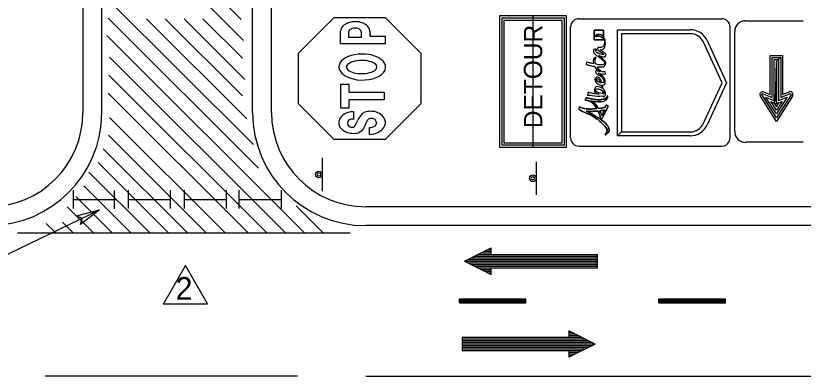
# Model space of a CAD drawing. Extents: x 1482 to 1692, y 225 to 494.
# Drawn here: x 1536.8 to 1587.3, y 314.2 to 337.4 of the extents above; entities that cross this region are included whole.
import ezdxf

# ---------------------------------------------------------------- set-up
doc = ezdxf.new("R2010")
doc.units = 0
for name, color, linetype in [('Level 10', 7, 'Continuous'), ('Level 17', 7, 'Continuous'), ('Level 2', 7, 'Continuous'), ('Level 53', 7, 'Continuous'), ('Level 60', 7, 'Continuous')]:
    doc.layers.add(name, color=color, linetype=linetype)

msp = doc.modelspace()

# ---------------------------------------------------------------- linework, layer by layer
at = {"layer": 'Level 10'}
for p, q in [((1540.474, 324.994), (1540.474, 326.173)), ((1543.997, 324.994), (1543.997, 326.173)), ((1546.697, 324.994), (1546.697, 326.173)), ((1547.586, 324.994), (1547.586, 326.173)), ((1550.286, 324.994), (1550.286, 326.173)), ((1551.109, 324.994), (1551.109, 326.173)), ((1553.809, 324.994), (1553.809, 326.173)), ((1540.474, 325.58), (1543.174, 325.58)), ((1543.997, 325.58), (1546.697, 325.58)), ((1547.586, 325.58), (1550.286, 325.58)), ((1551.109, 325.58), (1553.809, 325.58))]:
    msp.add_line(p, q, dxfattribs=at)
at = {"layer": 'Level 17'}
for p, q in [((1569.955, 328.928), (1569.955, 337.365)), ((1583.587, 337.047), (1587.284, 337.047)), ((1557.604, 335.58), (1557.604, 336.384)), ((1558.12, 336.312), (1558.12, 336)), ((1558.12, 336.312), (1558.12, 336)), ((1558.12, 336), (1558.956, 336)), ((1558.12, 336), (1558.956, 336)), ((1558.956, 336), (1558.956, 336.306)), ((1558.956, 336), (1558.956, 336.306)), ((1559.491, 336.343), (1559.498, 336.057)), ((1559.498, 336.057), (1559.498, 336.357)), ((1559.498, 336.057), (1560.478, 336.057)), ((1560.478, 336.057), (1560.478, 335.58)), ((1582.901, 329.932), (1582.901, 336.369)), ((1560.478, 335.58), (1557.604, 335.58)), ((1585.163, 332.308), (1585.163, 334.824)), ((1585.163, 334.824), (1585.963, 334.824)), ((1585.963, 334.824), (1585.963, 332.314)), ((1557.504, 334.053), (1557.502, 334.068)), ((1557.992, 334.033), (1557.988, 334.053)), ((1557.631, 331.446), (1557.631, 332.976)), ((1557.631, 332.976), (1558.146, 332.976)), ((1558.146, 332.976), (1558.146, 332.472)), ((1558.146, 332.472), (1560.394, 332.472)), ((1560.394, 332.472), (1560.394, 331.974)), ((1584.703, 332.5), (1585.163, 332.308)), ((1585.963, 332.308), (1586.425, 332.506)), ((1560.394, 331.974), (1558.134, 331.974)), ((1558.134, 331.974), (1558.134, 331.446)), ((1585.567, 330.586), (1584.536, 332.199)), ((1586.591, 332.199), (1585.567, 330.586)), ((1558.134, 331.446), (1557.631, 331.446)), ((1558.434, 331.212), (1558.434, 330.72)), ((1559.466, 329.755), (1559.466, 330.205)), ((1560.034, 329.898), (1560.032, 329.895)), ((1587.284, 329.248), (1583.587, 329.248)), ((1556.457, 326.107), (1556.457, 328.24)), ((1570.177, 325.863), (1570.177, 327.996)), ((1543.112, 324.972), (1543.112, 326.151)), ((1535.698, 321.794), (1542.151, 324.898))]:
    msp.add_line(p, q, dxfattribs=at)
for points in [[(1560.458, 337.269), (1562.752, 334.975), (1562.752, 331.709), (1560.458, 329.415), (1557.192, 329.415), (1554.9, 331.709), (1554.9, 334.975), (1557.192, 337.269)], [(1567.801, 337.359), (1567.801, 328.934), (1572.109, 328.934), (1572.109, 337.359)], [(1567.942, 337.22), (1567.942, 329.074), (1571.968, 329.074), (1571.968, 337.22)], [(1568.083, 337.078), (1568.083, 329.214), (1571.828, 329.214), (1571.828, 337.078)], [(1542.151, 324.898), (1540.934, 323.968), (1541.023, 324.355), (1540.665, 324.527)]]:
    msp.add_lwpolyline(points, close=True, dxfattribs=at)
for points in [[(1585.841, 334.689), (1585.841, 332.116), (1586.437, 332.372), (1586.501, 332.302), (1585.567, 330.824), (1584.619, 332.308), (1584.657, 332.379), (1585.291, 332.116), (1585.291, 334.695), (1585.841, 334.689), (1585.707, 334.568), (1585.707, 331.924), (1586.258, 332.148), (1585.567, 331.066), (1584.875, 332.148), (1585.425, 331.924), (1585.425, 334.568), (1585.707, 334.568), (1585.579, 334.432), (1585.579, 331.713), (1585.925, 331.86), (1585.567, 331.304), (1585.202, 331.874), (1585.406, 331.79), (1585.567, 331.534), (1585.727, 331.778), (1585.561, 331.726), (1585.406, 331.79), (1585.496, 331.918), (1585.561, 334.426), (1585.579, 334.432)], [(1585.841, 334.689), (1585.841, 332.116)]]:
    msp.add_lwpolyline(points, dxfattribs=at)
for centre, radius in [((1556.218, 327.178), 0.213), ((1556.218, 327.178), 0.107), ((1569.938, 326.934), 0.213), ((1569.938, 326.934), 0.107)]:
    msp.add_circle(centre, radius, dxfattribs=at)
for centre, radius, start, end in [((1558.358, 336.182), 0.778, 103.0674, 123.762), ((1558.587, 335.484), 1.512, 93.3903, 105.6597), ((1558.558, 335.78), 1.215, 79.7521, 92.7916), ((1558.558, 335.78), 1.215, 79.7521, 92.7916), ((1558.463, 335.418), 1.588, 68.3153, 78.6699), ((1583.585, 336.363), 0.692, 90, 180), ((1558.077, 336.342), 0.477, 134.8528, 175.0441), ((1558.286, 336.192), 0.732, 119.2241, 138.5308), ((1558.286, 336.192), 0.732, 119.2241, 138.5308), ((1558.392, 336.264), 0.283, 125.1198, 169.3117), ((1558.392, 336.264), 0.283, 125.1198, 169.3117), ((1558.476, 336.132), 0.44, 98.6031, 124.217), ((1558.476, 336.132), 0.44, 98.6031, 124.217), ((1558.533, 336.116), 0.468, 80.3417, 105.2342), ((1558.533, 336.116), 0.468, 80.3417, 105.2342), ((1558.59, 336.16), 0.418, 56.5086, 87.0313), ((1558.59, 336.16), 0.418, 56.5086, 87.0313), ((1558.638, 336.24), 0.325, 11.9191, 55.7868), ((1558.638, 336.24), 0.325, 11.9191, 55.7868), ((1558.767, 336.173), 0.774, 48.2922, 68.6031), ((1558.767, 336.173), 0.774, 48.2922, 68.6031), ((1558.989, 336.374), 0.478, 25.3838, 52.6188), ((1558.806, 336.231), 0.706, 16.602, 29.8091), ((1559.328, 336.373), 0.166, 349.7909, 23.5419), ((1584.703, 332.303), 0.199, 90.1051, 212.4986), ((1586.425, 332.306), 0.199, 327.5038, 90.1058), ((1558.022, 330.506), 0.532, 136.1369, 211.3987), ((1558.314, 330.284), 0.898, 104.564, 139.0063), ((1558.455, 329.966), 1.243, 90.6952, 107.1452), ((1559.8, 330.227), 1.175, 136.2465, 157.9263), ((1557.651, 332.628), 2.053, 309.479, 313.4261), ((1559.537, 330.014), 1.223, 95.9097, 111.9865), ((1559.534, 329.504), 1.731, 81.247, 93.9864), ((1559.413, 329.91), 1.361, 55.5092, 73.2894), ((1559.736, 330.391), 0.782, 23.1413, 54.9906), ((1558.325, 330.46), 0.277, 137.3017, 199.0119), ((1558.303, 330.481), 0.264, 203.8064, 262.2407), ((1558.373, 330.331), 0.405, 80.4412, 129.3244), ((1557.123, 331.213), 1.68, 327.9816, 340.979), ((1554.114, 332.527), 5.521, 334.4624, 338.8312), ((1559.599, 330.443), 0.348, 124.2083, 164.1552), ((1559.562, 330.453), 0.319, 82.5761, 120.4776), ((1559.6, 330.357), 0.413, 56.253, 88.7323), ((1559.597, 330.492), 0.31, 5.4374, 44.0625), ((1559.571, 330.517), 0.335, 320.6966, 1.4573), ((1560.001, 330.506), 0.489, 322.0536, 22.7397), ((1558.295, 330.706), 0.87, 213.3662, 245.6734), ((1558.401, 331.04), 1.219, 247.7332, 267.1392), ((1558.341, 330.45), 0.242, 254.131, 328.1476), ((1558.434, 330.889), 1.071, 264.8171, 285.9183), ((1558.466, 330.575), 0.762, 290.4481, 325.1107), ((1559.473, 330.885), 0.685, 269.0172, 283.5172), ((1559.399, 331.257), 1.502, 272.3841, 294.9519), ((1559.602, 330.563), 0.344, 276.8728, 312.7449), ((1559.525, 330.839), 1.07, 298.4154, 323.6553), ((1583.585, 329.933), 0.692, 180, 270)]:
    msp.add_arc(centre, radius, start, end, dxfattribs=at)
for centre, major_axis, ratio, start_param, end_param in [((1558.999, 334.08), (1.497, -0.01), 0.558644, 0.656861, 3.168126), ((1558.965, 334.08), (0.977, 0.005), 0.432619, 0.881967, 3.190734), ((1558.999, 334.08), (1.497, -0.01), 0.558644, 4.129576, 6.939747), ((1558.965, 334.08), (0.977, 0.005), 0.432619, 3.890436, 7.165085), ((1558.999, 334.08), (1.497, -0.01), 0.558644, 3.185857, 4.129398), ((1558.965, 334.08), (0.977, 0.005), 0.432619, 3.239639, 3.888884)]:
    msp.add_ellipse(centre, major_axis=major_axis, ratio=ratio, start_param=start_param, end_param=end_param, dxfattribs=at)
at = {"layer": 'Level 2'}
for p, q in [((1541.08, 370.179), (1541.08, 331.153)), ((1542.29, 331.153), (1542.29, 370.179)), ((1551.968, 331.153), (1551.968, 370.179)), ((1553.177, 331.153), (1553.177, 370.179)), ((1549.117, 339.254), (1551.241, 337.13)), ((1542.708, 338.422), (1552.014, 329.114)), ((1549.117, 338.047), (1551.39, 335.774)), ((1542.708, 337.215), (1552.347, 327.575)), ((1545.156, 337.181), (1551.589, 330.747)), ((1546.362, 337.181), (1551.323, 332.221)), ((1547.569, 337.181), (1551.474, 333.275)), ((1548.775, 337.181), (1551.308, 334.647)), ((1572.884, 337.18), (1582.071, 337.18)), ((1572.366, 329.52), (1572.366, 336.662)), ((1572.366, 329.52), (1572.366, 336.662)), ((1575.37, 329.662), (1575.37, 336.478)), ((1575.37, 336.478), (1580.038, 336.478)), ((1582.589, 329.52), (1582.589, 336.662)), ((1542.62, 336.095), (1555.293, 323.424)), ((1580.038, 336.222), (1575.625, 336.222)), ((1575.625, 336.222), (1575.625, 329.918)), ((1582.075, 333.07), (1580.891, 335.673)), ((1581.123, 335.779), (1582.355, 333.07)), ((1542.791, 334.718), (1554.083, 323.424)), ((1542.745, 333.557), (1552.876, 323.424)), ((1580.891, 330.467), (1582.075, 333.07)), ((1582.355, 333.07), (1581.123, 330.361)), ((1542.703, 332.393), (1551.671, 323.424)), ((1542.778, 330.842), (1550.196, 323.424)), ((1575.37, 329.662), (1575.625, 329.918)), ((1575.625, 329.918), (1575.37, 329.662)), ((1575.625, 329.918), (1580.038, 329.918)), ((1542.715, 329.697), (1548.988, 323.424)), ((1580.038, 329.662), (1575.37, 329.662)), ((1572.884, 329.002), (1582.071, 329.002)), ((1542.384, 328.821), (1547.782, 323.424)), ((1542.062, 327.938), (1546.576, 323.424)), ((1541.46, 327.335), (1545.37, 323.424)), ((1541.136, 326.451), (1544.164, 323.424)), ((1540.618, 325.764), (1542.958, 323.424)), ((1540.071, 325.105), (1541.752, 323.424)), ((1554.757, 325.165), (1556.498, 323.424)), ((1620.696, 325.105), (1559.225, 325.105)), ((1538.726, 324.038), (1539.34, 323.424)), ((1539.769, 324.107), (1540.452, 323.424)), ((1620.696, 323.894), (1559.225, 323.894)), ((1536.893, 323.424), (1558.225, 323.424)), ((1565.561, 321.612), (1567.267, 322.465)), ((1567.054, 322.359), (1567.267, 322.359)), ((1567.267, 322.039), (1567.267, 322.465)), ((1565.988, 321.825), (1574.094, 321.825)), ((1566.201, 321.932), (1574.094, 321.932)), ((1566.414, 322.039), (1574.094, 322.039)), ((1566.628, 322.145), (1567.267, 322.145)), ((1566.841, 322.252), (1567.267, 322.252)), ((1567.267, 322.039), (1574.094, 322.039)), ((1574.094, 321.185), (1574.094, 322.039)), ((1565.561, 321.612), (1574.094, 321.612)), ((1565.561, 321.612), (1567.267, 320.759)), ((1565.774, 321.719), (1574.094, 321.719)), ((1565.774, 321.505), (1574.094, 321.505)), ((1565.988, 321.399), (1574.094, 321.399)), ((1566.201, 321.292), (1574.094, 321.292)), ((1566.414, 321.185), (1574.094, 321.185)), ((1566.628, 321.079), (1567.267, 321.079)), ((1566.841, 320.972), (1567.267, 320.972)), ((1567.054, 320.865), (1567.267, 320.865)), ((1567.267, 321.185), (1574.094, 321.185)), ((1567.267, 320.759), (1567.267, 321.185)), ((1565.231, 319.189), (1569.498, 319.189)), ((1565.231, 318.933), (1565.231, 319.189)), ((1565.231, 319.125), (1569.498, 319.125)), ((1565.231, 319.061), (1569.498, 319.061)), ((1565.231, 318.997), (1569.498, 318.997)), ((1565.231, 318.933), (1569.498, 318.933)), ((1569.498, 318.933), (1569.498, 319.189)), ((1578.031, 319.189), (1582.297, 319.189)), ((1578.031, 318.933), (1578.031, 319.189)), ((1578.031, 319.125), (1582.297, 319.125)), ((1578.031, 319.061), (1582.297, 319.061)), ((1578.031, 318.997), (1582.297, 318.997)), ((1578.031, 318.933), (1582.297, 318.933)), ((1582.297, 318.933), (1582.297, 319.189)), ((1573.948, 316.288), (1572.241, 317.141)), ((1572.241, 317.141), (1572.241, 316.715)), ((1572.454, 317.035), (1572.241, 317.035)), ((1572.668, 316.928), (1572.241, 316.928)), ((1572.881, 316.821), (1572.241, 316.821)), ((1572.241, 316.715), (1565.415, 316.715)), ((1565.415, 316.715), (1565.415, 315.861)), ((1573.094, 316.715), (1565.415, 316.715)), ((1573.308, 316.608), (1565.415, 316.608)), ((1573.521, 316.501), (1565.415, 316.501)), ((1573.734, 316.395), (1565.415, 316.395)), ((1573.948, 316.288), (1565.415, 316.288)), ((1573.948, 316.288), (1572.241, 315.435)), ((1573.734, 316.181), (1565.415, 316.181)), ((1573.521, 316.075), (1565.415, 316.075)), ((1573.308, 315.968), (1565.415, 315.968)), ((1572.241, 315.861), (1565.415, 315.861)), ((1573.094, 315.861), (1565.415, 315.861)), ((1572.241, 315.861), (1572.241, 315.435)), ((1572.881, 315.755), (1572.241, 315.755)), ((1572.668, 315.648), (1572.241, 315.648)), ((1572.454, 315.541), (1572.241, 315.541)), ((1554.854, 314.218), (1538.653, 314.218)), ((1559.225, 314.218), (1620.696, 314.218))]:
    msp.add_line(p, q, dxfattribs=at)
for centre, radius, start, end in [((1572.884, 336.662), 0.518, 90, 180), ((1582.071, 336.662), 0.518, 360, 90), ((1580.038, 335.285), 1.193, 24.4568, 90), ((1580.038, 335.285), 0.937, 24.4568, 90), ((1535.032, 331.153), 6.048, 270, 360), ((1535.032, 331.153), 7.258, 270, 360), ((1559.225, 331.153), 7.258, 180, 270), ((1559.225, 331.153), 6.048, 180, 270), ((1580.038, 330.855), 0.937, 270, 335.5432), ((1580.038, 330.855), 1.193, 270, 335.5432), ((1572.884, 329.52), 0.518, 180, 270), ((1582.071, 329.52), 0.518, 270, 360)]:
    msp.add_arc(centre, radius, start, end, dxfattribs=at)
at = {"layer": 'Level 53'}
msp.add_line((1574.481, 336), (1574.481, 335.85), dxfattribs=at)
msp.add_lwpolyline([(1574.481, 336), (1574.481, 336.44), (1573.873, 336.44), (1573.873, 335.832), (1574.481, 335.832), (1574.481, 335.85)], dxfattribs=at)
for points, degree in [([(1573.873, 335.832), (1573.873, 335.832), (1574.481, 335.832), (1574.481, 335.832), (1574.481, 335.832), (1574.481, 335.85), (1574.481, 335.85), (1574.402, 335.982), (1574.251, 336.071), (1574.126, 336.07), (1574.019, 336.07), (1574.025, 336.013), (1574.01, 336.02), (1573.966, 336.038), (1573.991, 336.173), (1574.143, 336.18), (1574.271, 336.187), (1574.396, 336.12), (1574.481, 336), (1574.481, 336), (1574.481, 336.44), (1574.481, 336.44), (1574.481, 336.44), (1573.873, 336.44), (1573.873, 336.44), (1573.873, 336.44), (1573.873, 335.832), (1573.873, 335.832)], 3), ([(1574.481, 335.85), (1574.402, 335.982), (1574.251, 336.071), (1574.126, 336.07), (1574.019, 336.07), (1574.025, 336.013), (1574.01, 336.02), (1573.966, 336.038), (1573.991, 336.173), (1574.143, 336.18), (1574.271, 336.187), (1574.396, 336.12), (1574.481, 336)], 3), ([(1574.25, 335.189), (1574.375, 335.203), (1574.591, 335.287), (1574.591, 335.624), (1574.591, 335.776), (1574.549, 335.904), (1574.481, 336)], 3), ([(1574.535, 335.662), (1574.535, 335.412), (1574.341, 335.348), (1574.245, 335.336), (1574.181, 335.328), (1574.089, 335.342), (1574.101, 335.231), (1574.11, 335.154), (1574.26, 335.084), (1574.386, 334.987), (1574.495, 334.903), (1574.485, 334.865), (1574.391, 334.885), (1574.275, 334.909), (1574.001, 335.006), (1573.981, 335.118), (1573.971, 335.17), (1574.062, 335.188), (1574.005, 335.212), (1573.949, 335.236), (1573.826, 335.214), (1573.826, 335.098), (1573.826, 335.017), (1573.912, 334.92), (1574.009, 334.841), (1574.094, 334.772), (1574.61, 334.421), (1574.499, 334.274), (1574.447, 334.206), (1574.235, 334.211), (1573.985, 334.254)], 3), ([(1574.481, 335.85), (1574.514, 335.794), (1574.535, 335.73), (1574.535, 335.662)], 2), ([(1574.177, 334.821), (1574.353, 334.743), (1574.578, 334.698), (1574.613, 334.816), (1574.653, 334.953), (1574.425, 335.062), (1574.25, 335.189)], 3), ([(1573.834, 334.284), (1573.753, 334.302), (1573.67, 334.322), (1573.59, 334.345), (1573.517, 334.365), (1573.39, 334.425), (1573.366, 334.268), (1573.358, 334.218), (1573.382, 334.239), (1573.45, 334.223), (1573.574, 334.192), (1573.736, 334.154), (1573.898, 334.126)], 3), ([(1573.985, 334.254), (1573.918, 334.429), (1573.94, 334.574), (1573.979, 334.656), (1573.998, 334.696), (1573.996, 334.702), (1573.951, 334.685), (1573.886, 334.659), (1573.783, 334.519), (1573.83, 334.3), (1573.831, 334.294), (1573.833, 334.289), (1573.834, 334.284)], 3), ([(1574.062, 334.103), (1574.298, 334.075), (1574.509, 334.085), (1574.576, 334.192), (1574.699, 334.388), (1574.375, 334.667), (1574.177, 334.821)], 3), ([(1573.898, 334.126), (1573.973, 333.997), (1574.097, 333.877), (1574.261, 333.789)], 2), ([(1574.14, 333.677), (1574.287, 333.663), (1574.606, 333.567), (1574.59, 333.73), (1574.583, 333.793), (1574.573, 333.766), (1574.518, 333.77), (1574.326, 333.784), (1574.162, 333.944), (1574.062, 334.103)], 3), ([(1574.373, 333.06), (1574.366, 333.086), (1574.357, 333.11), (1574.348, 333.129), (1574.242, 333.37), (1574.081, 333.453), (1573.983, 333.392), (1573.89, 333.334), (1573.918, 333.168), (1574.056, 333.037), (1574.124, 332.972), (1574.241, 332.922), (1574.348, 332.916)], 3), ([(1574.261, 333.789), (1574.185, 333.804), (1574.102, 333.828), (1574.045, 333.83), (1573.986, 333.831), (1573.973, 333.791), (1573.969, 333.775), (1573.959, 333.74), (1573.976, 333.699), (1574.034, 333.658), (1574.169, 333.561), (1574.384, 333.439), (1574.474, 333.254), (1574.539, 333.121), (1574.474, 333.063), (1574.373, 333.06)], 3), ([(1574.408, 332.918), (1574.515, 332.931), (1574.597, 333.001), (1574.582, 333.164), (1574.56, 333.394), (1574.277, 333.599), (1574.14, 333.677)], 3), ([(1574.068, 333.189), (1573.994, 333.269), (1573.999, 333.309), (1574.019, 333.32), (1574.063, 333.343), (1574.216, 333.248), (1574.3, 333.066)], 3), ([(1574.3, 333.066), (1574.217, 333.082), (1574.127, 333.125), (1574.068, 333.189)], 2), ([(1574.348, 332.916), (1574.36, 332.861), (1574.37, 332.797), (1574.38, 332.726)], 2), ([(1574.446, 332.676), (1574.436, 332.757), (1574.423, 332.841), (1574.408, 332.918)], 2), ([(1574.199, 332.334), (1574.044, 332.346), (1573.856, 332.371), (1573.68, 332.406), (1573.607, 332.421), (1573.48, 332.471), (1573.456, 332.312), (1573.448, 332.261), (1573.471, 332.269), (1573.54, 332.273), (1573.632, 332.279), (1574.188, 332.177), (1574.432, 332.23)], 3), ([(1574.38, 332.726), (1574.196, 332.839), (1573.948, 332.829), (1573.907, 332.664), (1573.858, 332.472), (1574.044, 332.375), (1574.199, 332.334)], 3), ([(1574.415, 332.375), (1574.22, 332.4), (1573.949, 332.502), (1573.992, 332.628), (1574.017, 332.701), (1574.246, 332.663), (1574.398, 332.569)], 3), ([(1574.398, 332.569), (1574.404, 332.508), (1574.41, 332.443), (1574.415, 332.375)], 2), ([(1574.432, 332.23), (1574.454, 332.162), (1574.506, 332.134), (1574.56, 332.222), (1574.597, 332.283), (1574.61, 332.416), (1574.543, 332.551), (1574.519, 332.6), (1574.486, 332.641), (1574.446, 332.676)], 3), ([(1574.475, 332.369), (1574.474, 332.403), (1574.47, 332.457), (1574.464, 332.521)], 2), ([(1574.464, 332.521), (1574.501, 332.487), (1574.526, 332.45), (1574.532, 332.409)], 2), ([(1574.532, 332.409), (1574.536, 332.387), (1574.535, 332.369), (1574.533, 332.354)], 2), ([(1574.702, 332.187), (1574.692, 332.122), (1574.603, 332.036), (1574.456, 332.01), (1574.193, 331.964), (1573.933, 331.991), (1573.546, 332.069), (1573.472, 332.083), (1573.345, 332.133), (1573.321, 331.974), (1573.313, 331.924), (1573.338, 331.95), (1573.405, 331.936), (1573.694, 331.875), (1573.901, 331.639), (1574.041, 331.402), (1573.711, 331.377), (1573.344, 331.387), (1573.119, 331.449), (1572.929, 331.502), (1572.964, 331.564), (1572.924, 331.487), (1572.882, 331.405), (1572.937, 331.318), (1573.079, 331.247), (1573.22, 331.176), (1573.988, 330.85), (1574.506, 330.329), (1574.771, 330.062), (1574.635, 329.821), (1574.594, 329.773), (1574.561, 329.734), (1574.612, 329.719), (1574.664, 329.768), (1574.897, 329.983), (1574.763, 330.298), (1574.649, 330.413), (1574.332, 330.73), (1573.65, 331.099), (1573.36, 331.248), (1573.523, 331.234), (1573.797, 331.229), (1574.117, 331.26), (1574.196, 331.098), (1574.242, 330.954), (1574.26, 330.886), (1574.279, 330.812), (1574.309, 330.766), (1574.343, 330.765), (1574.381, 330.763), (1574.413, 330.813), (1574.447, 330.884), (1574.507, 331.012), (1574.684, 331.386), (1574.737, 331.478), (1574.783, 331.557), (1574.747, 331.596), (1574.698, 331.619), (1574.634, 331.65), (1574.596, 331.566), (1574.572, 331.485), (1574.464, 331.454), (1574.318, 331.429), (1574.157, 331.412), (1574.04, 331.602), (1573.884, 331.789), (1573.689, 331.897), (1573.852, 331.87), (1574.406, 331.8), (1574.64, 331.975), (1574.691, 332.014), (1574.748, 332.099), (1574.739, 332.182), (1574.735, 332.221), (1574.71, 332.24), (1574.702, 332.237), (1574.694, 332.233), (1574.705, 332.21), (1574.702, 332.187)], 3), ([(1574.702, 332.187), (1574.692, 332.122), (1574.603, 332.036), (1574.456, 332.01), (1574.193, 331.964), (1573.933, 331.991), (1573.546, 332.069), (1573.472, 332.083), (1573.345, 332.133), (1573.321, 331.974), (1573.313, 331.924), (1573.338, 331.95), (1573.405, 331.936), (1573.694, 331.875), (1573.901, 331.639), (1574.041, 331.402)], 3), ([(1573.689, 331.897), (1573.852, 331.87), (1574.406, 331.8), (1574.64, 331.975), (1574.691, 332.014), (1574.748, 332.099), (1574.739, 332.182), (1574.735, 332.221), (1574.71, 332.24), (1574.702, 332.237), (1574.694, 332.233), (1574.705, 332.21), (1574.702, 332.187)], 3), ([(1574.157, 331.412), (1574.04, 331.602), (1573.884, 331.789), (1573.689, 331.897)], 2), ([(1574.533, 332.354), (1574.525, 332.363), (1574.514, 332.368), (1574.501, 332.368), (1574.493, 332.368), (1574.484, 332.368), (1574.475, 332.369)], 3), ([(1574.041, 331.402), (1573.711, 331.377), (1573.344, 331.387), (1573.119, 331.449), (1572.929, 331.502), (1572.964, 331.564), (1572.924, 331.487), (1572.882, 331.405), (1572.937, 331.318), (1573.079, 331.247), (1573.22, 331.176), (1573.988, 330.85), (1574.506, 330.329), (1574.771, 330.062), (1574.635, 329.821), (1574.594, 329.773), (1574.561, 329.734), (1574.612, 329.719), (1574.664, 329.768), (1574.897, 329.983), (1574.763, 330.298), (1574.649, 330.413), (1574.332, 330.73), (1573.65, 331.099), (1573.36, 331.248)], 3), ([(1574.117, 331.26), (1574.196, 331.098), (1574.242, 330.954), (1574.26, 330.886), (1574.279, 330.812), (1574.309, 330.766), (1574.343, 330.765), (1574.381, 330.763), (1574.413, 330.813), (1574.447, 330.884), (1574.507, 331.012), (1574.684, 331.386), (1574.737, 331.478), (1574.783, 331.557), (1574.747, 331.596), (1574.698, 331.619), (1574.634, 331.65), (1574.596, 331.566), (1574.572, 331.485)], 3), ([(1574.572, 331.485), (1574.464, 331.454), (1574.318, 331.429), (1574.157, 331.412)], 2), ([(1573.36, 331.248), (1573.523, 331.234), (1573.797, 331.229), (1574.117, 331.26)], 2), ([(1574.236, 331.272), (1574.365, 331.288), (1574.459, 331.304), (1574.528, 331.323)], 2), ([(1574.371, 330.968), (1574.34, 331.053), (1574.295, 331.16), (1574.236, 331.272)], 2), ([(1574.371, 330.968), (1574.34, 331.053), (1574.295, 331.16), (1574.236, 331.272), (1574.365, 331.288), (1574.459, 331.304), (1574.528, 331.323), (1574.498, 331.24), (1574.45, 331.122), (1574.371, 330.968)], 3), ([(1574.528, 331.323), (1574.498, 331.24), (1574.45, 331.122), (1574.371, 330.968)], 2)]:
    msp.add_open_spline(points, degree=degree, dxfattribs=at)
at = {"layer": 'Level 60'}
for points in [[(1547.657, 321.341), (1546.264, 318.916)], [(1549.051, 318.916), (1547.657, 321.341)], [(1546.264, 318.916), (1546.238, 318.871), (1549.077, 318.871), (1549.051, 318.916)]]:
    msp.add_lwpolyline(points, dxfattribs=at)

# ---------------------------------------------------------------- texts
at = {"layer": 'Level 17'}
msp.add_text('DETOUR', height=1.1758, rotation=90, dxfattribs=at).set_placement((1570.543, 330.154))
at = {"layer": 'Level 60'}
msp.add_text('2', height=1.448, rotation=360, dxfattribs=at).set_placement((1547.03, 319.14))

doc.saveas('drawing.dxf')
